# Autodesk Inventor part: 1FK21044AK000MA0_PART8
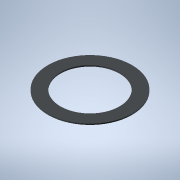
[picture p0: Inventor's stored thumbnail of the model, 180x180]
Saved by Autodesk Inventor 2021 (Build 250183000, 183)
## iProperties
Created: 2025-04
Part Number: 1FK21044AK000MA0_PART8
Material: Generic
Catalog Web Link: www.3dfindit.com
Description: -Servo synchronous motor
Document SubType Name: Modeling
Designer: psAdmin
Mass: 0.27214 g
Surface Area: 11.8752 cm^2
Volume: 0.27214 cm^3
Density: 1 g/cm^3
Appearance: PSOLRGB-212-217-219
Category: PARTsolutions
Title: 1FK21044AK000MA0_PART8
Author: Cadenas PARTsolutions
Comments: Servo synchronous motor
Sending System: PARTsolutions
Preprocessor: ST-DEVELOPER v19.3
PSOL_IDENT_0: {$CADENAS_DATA/23d-libs/siemens_ag/_cat_/87/f4/1fk21044ak000ma0.prj},213 {VTYP=3D},{NB=1FK21044AK000
PSOL_IDENT_1: MA0_PART8},{LINA=1FK21044AK000MA0_PART8},{NN=1FK21044AK000MA0_PART8},{NOPRJ=TRUE},{DATE=19.08.2025 1
PSOL_IDENT_2: 4:00:48},{GEOMDATE=30.07.2025 02:00:50},{VERSION=},{LINEID=10},{WBVAR=},{WBNUMERIC=}  {NB=1FK21044AK
PSOL_IDENT_3: 000MA0_PART8},{LINA=1FK21044AK000MA0_PART8},{KT=DUMMY},{PREVIEW=../../../_pool_/cb/72/p_d211_xx_0043
PSOL_IDENT_4: 4j.png},{DESCSHORT=SIMOTICS S-1FK2 HD, SINAMICS S210 3AC 400V-480V, 0.95 Nm, 6000 rpm},{DESCLONG=SIM
PSOL_IDENT_5: OTICS S-1FK2 HD servo motor M0=1.27 Nm; PN = 0.6 kW at nN=6000 rpm (380-480 V); PN = 0.4 kW at nN=30
PSOL_IDENT_6: 00 rpm (200-240 V); degree of protection IP64; cylindrical shaft D19x40mm; absolute encoder 22-bit +
PSOL_IDENT_7: 12-bit multiturn (encoder AM22DQC); with OCC interface; plug size M17, rotatable; SIMOTICS S-1FK2 s
PSOL_IDENT_8: ervomotorfor a wide range of uses in industrial environments. SIMOTICS S‑1FK2 servomotors are compac
PSOL_IDENT_9: t synchronous motors with a high dynamic performance that set themselves apart as a result of their
PSOL_IDENT_10: high power density, degree of protection and overload capability. The motors are available in two va
PSOL_IDENT_11: riants: as High Dynamic variant (highest dynamic performance as a result of the low intrinsic moment
PSOL_IDENT_12: of inertia for applications demanding a high dynamic performance with low moved masses) - and as Co
PSOL_IDENT_13: mpact variant (precise and stable closed-loop control for medium up to large moved masses as a resul
PSOL_IDENT_14: t of a medium intrinsic moment of inertia). SIMOTICSS‑1FK2 servomotors fully exploit their strengths
PSOL_IDENT_15: in a system with the SINAMICSS210 frequency converter and simple connection using the one cable con
PSOL_IDENT_16: nection (OCC). Advantages include the short control and positioning times, fast and precise correcti
PSOL_IDENT_17: on of disturbing quantities as well as stable control with a high dynamic performance. The servo mot
PSOL_IDENT_18: ors can be configured to address a wide range of requirements. For example with and without holding
PSOL_IDENT_19: brake, IP64 or IP65 degree of protection, singleturn or multiturn absolute encoders - to name just a
PSOL_IDENT_20: few. Further, the servomotors are available in different shaft heights extending from 20 to 100. A
PSOL_IDENT_21: shaft sealing ring is available to achieve an IP65 degree of protection and for subsequent mounting
PSOL_IDENT_22: at the motor or as spare part. SIMOTICS - the optimum motor for each and every motion control applic
PSOL_IDENT_23: ation.},{INTNO=195125056312},{SUPPLIERALTNO=1FK2104-4AK00-0MA0},{MANUID=1FK21044AK000MA0},{MANUNAME=
PSOL_IDENT_24: Siemens},{MANUTYPEDESC=Synchronous motor 1FK2-HD 1,27 Nm},{AAU732=SIMOTICS},{AAO057=S-1FK2},{AAU734=
PSOL_IDENT_25: SIMOTICS S-1FK2 HD servo motor M0=1.27 Nm; PN = 0.6 kW at nN=6000 rpm (380-480 V); PN = 0.4 kW at nN=
PSOL_IDENT_26: 3000 rpm (200-240 V); degree of protection IP64; cylindrical shaft D19x40mm; absolute encoder 22-bit
PSOL_IDENT_27: + 12-bit multiturn (encoder AM22DQC); with OCC interface; plug size M17, rotatable;},{AAW338=Synchr
PSOL_IDENT_28: onous motor 1FK2-HD 1,27 Nm},{AAO742=SIMOTICS},{AAO663=4042948690994},{NOCUPEROU=1},{PRICEQUANTITY=1
PSOL_IDENT_29: },{QUANTITYMIN=1},{QUANTITYINT=1},{CTN=85015100},{COO=DE},{AAO676=1FK2104-4AK00-0MA0},{AAO677=Siemen
PSOL_IDENT_30: s AG},{ORDERUNIT=C62},{CONTENTUNIT=C62}
NB: 1FK21044AK000MA0_PART8
NT: Servo synchronous motor
NBSYN: $MANUID._PART8
LINA: 1FK21044AK000MA0_PART8
CATALOG: SIEMENS
PREVIEW: ../../../_pool_/cb/72/p_d211_xx_00434j.png
DESCSHORT: SIMOTICS S-1FK2 HD, SINAMICS S210 3AC 400V-480V, 0.95 Nm, 6000 rpm
DESCLONG: SIMOTICS S-1FK2 HD servo motor M0=1.27 Nm; PN = 0.6 kW at nN=6000 rpm (380-480 V); PN = 0.4 kW at nN=3000 rpm (200-240 V); degree of protection IP64; cylindrica
INTNO: 195125056312
SUPPLIERALTNO: 1FK2104-4AK00-0MA0
MANUID: 1FK21044AK000MA0
MANUNAME: Siemens
MANUTYPEDESC: Synchronous motor 1FK2-HD 1,27 Nm
AAU732: SIMOTICS
AAO057: S-1FK2
AAU734: SIMOTICS S-1FK2 HD servo motor M0=1.27 Nm; PN = 0.6 kW at nN=6000 rpm (380-480 V); PN = 0.4 kW at nN=3000 rpm (200-240 V); degree of protection IP64; cylindrica
AAW338: Synchronous motor 1FK2-HD 1,27 Nm
AAO742: SIMOTICS
AAO663: 4042948690994.0
NOCUPEROU: 1
PRICEQUANTITY: 1
QUANTITYMIN: 1
QUANTITYINT: 1
CTN: 85015100
COO: DE
ARTICLENO: 1FK21044AK000MA0_PART8
BOMINFO: 1FK21044AK000MA0_PART8
CREATOR: CADENAS GmbH
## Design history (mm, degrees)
feature "2025_04_17_15_37_40_0588"
body "Solid1"
